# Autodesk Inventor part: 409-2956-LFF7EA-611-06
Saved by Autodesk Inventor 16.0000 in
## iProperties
Created: 2010-06
Part Number: 409-2956-LFF7EA-611-06
Cost Center: 0 lbmass
Material: A36 STEEL PLATE
Document SubType Name: Sheet Metal
Designer: S. Boerckel
Authority: 0 in^3
Mass: 2173.54 g
Surface Area: 679.837 cm^2
Volume: 276.532 cm^3
Density: 7.86 g/cm^3
Flat Pattern Width: 45.72 cm
Flat Pattern Length: 6.35 cm
Flat Pattern Area: 290.322 cm^2
Sheet Metal Rule: 3/8"Thk
Sheet Metal Width: 4.4375 in
Sheet Metal Length: 71.0000 in^2
Description: PUMP MOUNT END GUSSET
User Status: BURN
SaveDate: 2008-01-15
SaveTime: 10:24
FileName: Sheet Metal
Wide: =<Flat Pattern Width>cm
Length: =<Flat Pattern Length>cm
Thickness: 0.3750 in
SMR: =<Sheet Metal Rule> - <Material>
Author: S. Boerckel
Revision Number: 0
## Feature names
1. Plate1
2. Cut1
